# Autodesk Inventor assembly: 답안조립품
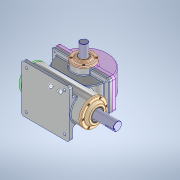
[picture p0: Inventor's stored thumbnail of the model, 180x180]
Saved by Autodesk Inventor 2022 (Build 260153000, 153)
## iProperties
Created: 2023-07
Part Number: 답안조립품
Document SubType Name: Assembly
Designer: PC-01
Author: PC-01
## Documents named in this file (14)
- C:\Users\PC-01\Desktop\730706V1016\답안조립품.iam
- C:\Users\PC-01\Desktop\730706V1016\본체.ipt
- C:\Users\PC-01\Desktop\730706V1016\웜 샤프트.ipt
- C:\Users\PC-01\Desktop\730706V1016\깊은 홈 볼 베어링 6209.ipt
- C:\Users\PC-01\Desktop\730706V1016\뒤커버.ipt
- C:\Users\PC-01\Desktop\730706V1016\육각 소켓 머리 볼트 M5 x 12.ipt
- C:\Users\PC-01\Desktop\730706V1016\앞커버.ipt
- C:\Users\PC-01\Desktop\730706V1016\오일 실 35 55 11.ipt
- C:\Users\PC-01\Desktop\730706V1016\웜 휠.ipt
- C:\Users\PC-01\Desktop\730706V1016\본체 커버.ipt
- C:\Users\PC-01\Desktop\730706V1016\육각 소켓 머리 볼트 M6 x 20.ipt
- C:\Users\PC-01\Desktop\730706V1016\오일 실 30 42 7.ipt
- C:\Users\PC-01\Desktop\730706V1016\깊은 홈 볼 베어링 6206.ipt
- C:\Users\PC-01\Desktop\730706V1016\서브커버.ipt
